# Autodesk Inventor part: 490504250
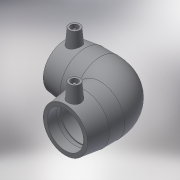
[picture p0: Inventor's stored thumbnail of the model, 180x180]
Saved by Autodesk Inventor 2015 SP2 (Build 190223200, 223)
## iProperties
Created: 2017-06
Part Number: 490504250
Material: Generic
Description: PLASSON 90° ELBOW 250
Document SubType Name: Modeling
Designer: KIM
Mass: 55.0731 g
Surface Area: 148.067 cm^2
Volume: 55.0731 cm^3
Density: 1 g/cm^3
Appearance: Default
Author: KIM
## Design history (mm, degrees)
derived "490504.ipt"
feature "Solid1::490504.ipt"
tag "TaggingFeature1"
body "Solid1"
other parameters: "d2" = 327, "d4" = 137.5, "d5" = 294.3, "d8" = 168 deg, "d10" = 52, "d11" = 17.33333, "d14" = 17.6296, "d19" = 3.52592, "d20" = 168 deg, "d22" = 300.84, "d23" = 327, "d24" = 291.8148, "d29" = 152, "d30" = 15, "d31" = 192.5, "d34" = 5 deg, "d35" = 15, "d39" = 5 deg, "d41" = 4, "d42" = 14, "d43" = 0, "d45" = 4, "d46" = 14, "d47" = 0, "d50" = 212.5, "d51" = 52, "d54" = 90 deg, "d67" = 45 deg, "d71" = 90 deg, "d75" = 16.35, "d82" = 45 deg, "d84" = 294.3, "d86" = 147.15, "d87" = 90 deg, "d91" = 0, "d93" = 0, "d94" = 90 deg, "d95" = 150.42, "d101" = 3, "d102" = 0, "d103" = 3, "d104" = 0, "d105" = 37.7, "d106" = 9.425, "d110" = 71.5, "D_" = 327, "A_" = 152, "d_2" = 12
